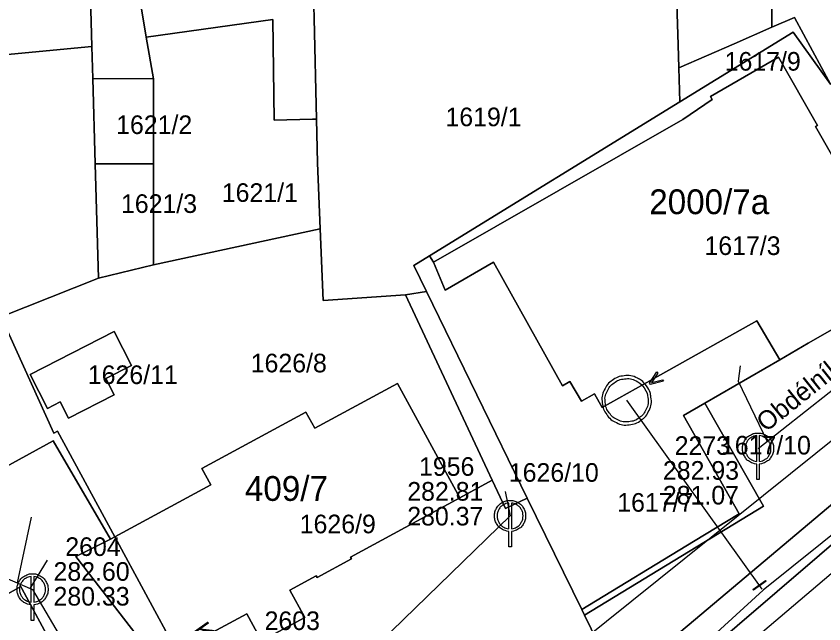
# Model space of a CAD drawing. Extents: x -570698 to -570232, y -1086952 to -1086596.
# Drawn here: x -570540.7 to -570475.5, y -1086825.7 to -1086776.7 of the extents above; entities that cross this region are included whole.
import ezdxf

# ---------------------------------------------------------------- set-up
doc = ezdxf.new("R2010")
doc.units = 0
for name, color, linetype in [('Adresní místo-text', 7, 'Continuous'), ('Armatura vodovodní', 7, 'Continuous'), ('Default', 7, 'Continuous'), ('Kanalizační přípojka', 7, 'Continuous'), ('Kanalizační stoka', 7, 'Continuous'), ('Kanalizační šachta', 7, 'Continuous'), ('Parcela-polygon', 7, 'Continuous'), ('Parcela-text', 7, 'Continuous'), ('Popis kmenové stoky', 7, 'Continuous'), ('Popis šachty', 7, 'Continuous'), ('Vodovodní přípojka', 7, 'Continuous'), ('Vodovodní řad', 7, 'Continuous'), ('Vodovodní šachta', 7, 'Continuous')]:
    doc.layers.add(name, color=color, linetype=linetype)

msp = doc.modelspace()

# ---------------------------------------------------------------- linework, layer by layer
at = {"layer": 'Armatura vodovodní'}
msp.add_lwpolyline([(-570480.197, -1086822.262), (-570481.212, -1086822.991), (-570481.257, -1086822.928), (-570480.242, -1086822.198), (-570480.197, -1086822.262)], dxfattribs=at)
at = {"layer": 'Default'}
for points in [[(-570489.836, -1086806.525), (-570489.544, -1086806.93), (-570489.475, -1086807.463), (-570489.406, -1086807.996), (-570489.636, -1086808.492), (-570489.867, -1086808.988), (-570490.289, -1086809.292), (-570490.705, -1086809.591), (-570491.239, -1086809.653), (-570491.774, -1086809.714), (-570492.261, -1086809.484), (-570492.749, -1086809.253), (-570493.05, -1086808.834), (-570493.347, -1086808.421), (-570493.41, -1086807.885), (-570493.473, -1086807.349), (-570493.244, -1086806.863), (-570493.015, -1086806.376), (-570492.598, -1086806.077), (-570492.176, -1086805.774), (-570491.635, -1086805.711), (-570491.093, -1086805.648), (-570490.61, -1086805.884), (-570490.127, -1086806.12), (-570489.836, -1086806.525)], [(-570490.035, -1086806.668), (-570490.289, -1086806.316), (-570490.713, -1086806.109), (-570491.137, -1086805.903), (-570491.611, -1086805.957), (-570492.085, -1086806.012), (-570492.455, -1086806.277), (-570492.818, -1086806.538), (-570493.019, -1086806.965), (-570493.22, -1086807.391), (-570493.166, -1086807.859), (-570493.111, -1086808.327), (-570492.85, -1086808.691), (-570492.585, -1086809.06), (-570492.159, -1086809.261), (-570491.732, -1086809.462), (-570491.264, -1086809.407), (-570490.796, -1086809.353), (-570490.432, -1086809.092), (-570490.063, -1086808.826), (-570489.862, -1086808.392), (-570489.661, -1086807.957), (-570489.721, -1086807.49), (-570489.78, -1086807.024), (-570490.035, -1086806.668)], [(-570489.359, -1086806.145), (-570489.414, -1086806.222), (-570489.463, -1086806.282), (-570489.382, -1086806.254), (-570489.298, -1086806.231)], [(-570480.953, -1086812.818), (-570481.211, -1086812.8), (-570481.473, -1086812.654), (-570481.77, -1086812.49), (-570481.935, -1086812.193), (-570482.1, -1086811.895), (-570482.1, -1086811.57), (-570482.1, -1086811.243), (-570481.932, -1086810.943), (-570481.763, -1086810.642), (-570481.465, -1086810.481), (-570481.167, -1086810.32), (-570480.85, -1086810.32), (-570480.535, -1086810.32), (-570480.236, -1086810.481), (-570479.937, -1086810.642), (-570479.768, -1086810.943), (-570479.6, -1086811.243), (-570479.6, -1086811.57), (-570479.6, -1086811.895), (-570479.765, -1086812.193), (-570479.93, -1086812.49), (-570480.227, -1086812.654), (-570480.489, -1086812.8), (-570480.747, -1086812.818)], [(-570480.953, -1086810.532), (-570481.15, -1086810.549), (-570481.365, -1086810.664), (-570481.614, -1086810.799), (-570481.753, -1086811.049), (-570481.892, -1086811.299), (-570481.892, -1086811.57), (-570481.892, -1086811.841), (-570481.756, -1086812.088), (-570481.619, -1086812.334), (-570481.37, -1086812.471), (-570481.158, -1086812.591), (-570480.953, -1086812.605)], [(-570480.747, -1086812.605), (-570480.542, -1086812.591), (-570480.328, -1086812.471), (-570480.081, -1086812.334), (-570479.944, -1086812.088), (-570479.808, -1086811.841), (-570479.808, -1086811.57), (-570479.808, -1086811.299), (-570479.948, -1086811.049), (-570480.088, -1086810.799), (-570480.337, -1086810.664), (-570480.55, -1086810.549), (-570480.747, -1086810.532)], [(-570500.943, -1086818.248), (-570501.201, -1086818.23), (-570501.463, -1086818.084), (-570501.76, -1086817.92), (-570501.925, -1086817.623), (-570502.09, -1086817.325), (-570502.09, -1086817), (-570502.09, -1086816.673), (-570501.922, -1086816.373), (-570501.753, -1086816.072), (-570501.455, -1086815.911), (-570501.157, -1086815.75), (-570500.84, -1086815.75), (-570500.525, -1086815.75), (-570500.226, -1086815.911), (-570499.927, -1086816.072), (-570499.758, -1086816.373), (-570499.59, -1086816.673), (-570499.59, -1086817), (-570499.59, -1086817.325), (-570499.755, -1086817.623), (-570499.92, -1086817.92), (-570500.217, -1086818.084), (-570500.479, -1086818.23), (-570500.737, -1086818.248)], [(-570500.943, -1086815.962), (-570501.14, -1086815.979), (-570501.355, -1086816.094), (-570501.604, -1086816.229), (-570501.743, -1086816.479), (-570501.882, -1086816.729), (-570501.882, -1086817), (-570501.882, -1086817.271), (-570501.746, -1086817.518), (-570501.609, -1086817.764), (-570501.36, -1086817.901), (-570501.148, -1086818.021), (-570500.943, -1086818.035)], [(-570500.737, -1086818.035), (-570500.532, -1086818.021), (-570500.318, -1086817.901), (-570500.071, -1086817.764), (-570499.934, -1086817.518), (-570499.798, -1086817.271), (-570499.798, -1086817), (-570499.798, -1086816.729), (-570499.938, -1086816.479), (-570500.078, -1086816.229), (-570500.327, -1086816.094), (-570500.54, -1086815.979), (-570500.737, -1086815.962)], [(-570539.443, -1086824.168), (-570539.701, -1086824.15), (-570539.963, -1086824.004), (-570540.26, -1086823.84), (-570540.425, -1086823.543), (-570540.59, -1086823.245), (-570540.59, -1086822.92), (-570540.59, -1086822.593), (-570540.422, -1086822.293), (-570540.253, -1086821.992), (-570539.955, -1086821.831), (-570539.657, -1086821.67), (-570539.34, -1086821.67), (-570539.025, -1086821.67), (-570538.726, -1086821.831), (-570538.427, -1086821.992), (-570538.258, -1086822.293), (-570538.09, -1086822.593), (-570538.09, -1086822.92), (-570538.09, -1086823.245), (-570538.255, -1086823.543), (-570538.42, -1086823.84), (-570538.717, -1086824.004), (-570538.979, -1086824.15), (-570539.237, -1086824.168)], [(-570539.443, -1086821.882), (-570539.64, -1086821.899), (-570539.855, -1086822.014), (-570540.104, -1086822.149), (-570540.243, -1086822.399), (-570540.382, -1086822.649), (-570540.382, -1086822.92), (-570540.382, -1086823.191), (-570540.246, -1086823.438), (-570540.109, -1086823.684), (-570539.86, -1086823.821), (-570539.648, -1086823.941), (-570539.443, -1086823.955)], [(-570539.237, -1086823.955), (-570539.032, -1086823.941), (-570538.818, -1086823.821), (-570538.571, -1086823.684), (-570538.434, -1086823.438), (-570538.298, -1086823.191), (-570538.298, -1086822.92), (-570538.298, -1086822.649), (-570538.438, -1086822.399), (-570538.578, -1086822.149), (-570538.827, -1086822.014), (-570539.04, -1086821.899), (-570539.237, -1086821.882)]]:
    msp.add_open_spline(points, degree=3, dxfattribs=at)
at = {"layer": 'Kanalizační přípojka'}
for points in [[(-570482.279, -1086804.912), (-570482.45, -1086806.15)], [(-570482.45, -1086806.15), (-570480.118, -1086810.992)], [(-570501.237, -1086815.04), (-570500.84, -1086817)], [(-570539.44, -1086817.11), (-570540.582, -1086822.397)], [(-570538.16, -1086820.56), (-570539.545, -1086822.838)]]:
    msp.add_lwpolyline(points, dxfattribs=at)
at = {"layer": 'Kanalizační stoka'}
msp.add_line((-570516.073, -1086843.915), (-570416.01, -1086763.66), dxfattribs=at)
for points in [[(-570480.85, -1086811.57), (-570469.4, -1086802.53), (-570457.95, -1086793.49)], [(-570483.53, -1086828.91), (-570466.92, -1086814.815), (-570450.31, -1086800.72)], [(-570500.84, -1086817), (-570516.12, -1086831.85)], [(-570541.982, -1086821.803), (-570539.34, -1086822.925)], [(-570539.34, -1086822.925), (-570534.7, -1086830.82)]]:
    msp.add_lwpolyline(points, dxfattribs=at)
at = {"layer": 'Kanalizační šachta'}
for points in [[(-570480.953, -1086812.605), (-570480.953, -1086810.532)], [(-570480.747, -1086810.532), (-570480.747, -1086812.605)], [(-570480.747, -1086812.818), (-570480.747, -1086814.07), (-570480.953, -1086814.07), (-570480.953, -1086812.818)], [(-570500.943, -1086818.035), (-570500.943, -1086815.962)], [(-570500.737, -1086815.962), (-570500.737, -1086818.035)], [(-570500.737, -1086818.248), (-570500.737, -1086819.5), (-570500.943, -1086819.5), (-570500.943, -1086818.248)], [(-570539.443, -1086823.955), (-570539.443, -1086821.882)], [(-570539.237, -1086821.882), (-570539.237, -1086823.955)], [(-570539.237, -1086824.168), (-570539.237, -1086825.42), (-570539.443, -1086825.42), (-570539.443, -1086824.168)]]:
    msp.add_lwpolyline(points, dxfattribs=at)
at = {"layer": 'Parcela-polygon'}
for points in [[(-570291.64, -1086688.892), (-570302.37, -1086696.04), (-570396.95, -1086758.9), (-570417.85, -1086767.9), (-570426.99, -1086775.07), (-570430.55, -1086777.63), (-570432.81, -1086779.33), (-570437.1, -1086782.56), (-570450.62, -1086793.64), (-570452.87, -1086797.51), (-570456.3, -1086803.42), (-570469.27, -1086814.47), (-570499.22, -1086840.17), (-570503.94, -1086844.12), (-570508.33, -1086847.72), (-570512.7, -1086850.77), (-570519.4, -1086855.31), (-570522.96, -1086857.62), (-570528.66, -1086861.02), (-570535.32, -1086864.67), (-570544.494, -1086869.551)], [(-570516.84, -1086768.72), (-570516.64, -1086776.92), (-570516.45, -1086785.02), (-570516.36, -1086788.54), (-570516.14, -1086793.85), (-570515.9, -1086799.64), (-570509.28, -1086799.19), (-570507.59, -1086798.91), (-570508.61, -1086796.82), (-570507.34, -1086796.04), (-570487.15, -1086783.62), (-570487.24, -1086780.88), (-570487.29, -1086779.03), (-570487.44, -1086773.99)], [(-570544.494, -1086869.551), (-570535.32, -1086864.67), (-570528.66, -1086861.02), (-570522.96, -1086857.62), (-570519.4, -1086855.31), (-570512.7, -1086850.77), (-570508.33, -1086847.72), (-570503.94, -1086844.12), (-570499.22, -1086840.17), (-570469.27, -1086814.47), (-570456.3, -1086803.42), (-570452.87, -1086797.51), (-570485.9, -1086825.32), (-570492.12, -1086830.55), (-570513.86, -1086848.7), (-570520.15, -1086853.96), (-570542.94, -1086866), (-570545.975, -1086867.584)], [(-570468.67, -1086798.42), (-570476.82, -1086803.09), (-570479.1, -1086804.43), (-570485.13, -1086807.9), (-570480.4, -1086816.21), (-570494.84, -1086825), (-570492.12, -1086830.55), (-570485.9, -1086825.32), (-570452.87, -1086797.51)], [(-570568.236, -1086838.021), (-570542.59, -1086823.97), (-570547, -1086816.06), (-570537.68, -1086810.96), (-570533.06, -1086818.87), (-570532.7, -1086818.69), (-570537.33, -1086810.17), (-570537.63, -1086810.34), (-570541.87, -1086800.95), (-570571.88, -1086812.78), (-570570.98, -1086827.68), (-570570.535, -1086834.968)], [(-570545.975, -1086867.584), (-570542.94, -1086866), (-570520.15, -1086853.96), (-570513.86, -1086848.7), (-570535.84, -1086820.27), (-570533.06, -1086818.87), (-570537.68, -1086810.96), (-570547, -1086816.06), (-570542.59, -1086823.97), (-570540.28, -1086822.7), (-570540.19, -1086822.86), (-570530.15, -1086841.46), (-570555.373, -1086855.104)], [(-570555.373, -1086855.104), (-570530.15, -1086841.46), (-570540.19, -1086822.86), (-570540.28, -1086822.7), (-570542.59, -1086823.97), (-570568.236, -1086838.021)]]:
    msp.add_lwpolyline(points, dxfattribs=at)
for points in [[(-570538.98, -1086751.22), (-570541.1, -1086771.74), (-570576.24, -1086767.98), (-570574.78, -1086782.97), (-570568.21, -1086782.35), (-570534.55, -1086779.16), (-570535.32, -1086751.53)], [(-570535.32, -1086751.53), (-570534.55, -1086779.16), (-570534.47, -1086781.74), (-570529.59, -1086781.76), (-570530.17, -1086778.41), (-570531.51, -1086770.26), (-570531.68, -1086762.98), (-570531.29, -1086759.87), (-570530.75, -1086752.07)], [(-570530.75, -1086752.07), (-570531.29, -1086759.87), (-570531.68, -1086762.98), (-570531.51, -1086770.26), (-570530.17, -1086778.41), (-570519.97, -1086777), (-570519.85, -1086785.1), (-570516.78, -1086785.02), (-570516.45, -1086785.02), (-570516.64, -1086776.92), (-570516.84, -1086768.72), (-570517.12, -1086757.38), (-570517.21, -1086753.48)], [(-570487.97, -1086756.56), (-570487.83, -1086761.17), (-570487.72, -1086764.85), (-570479.93, -1086765.93), (-570479.67, -1086764.1), (-570479.5, -1086762.88), (-570477.97, -1086763.08), (-570477.77, -1086761.55), (-570467.33, -1086762.82), (-570468.61, -1086773.22), (-570473.69, -1086772.58), (-570473.67, -1086772.43), (-570479.75, -1086771.68), (-570479.73, -1086777.62), (-570477.91, -1086776.82), (-570475.02, -1086782.19), (-570473.93, -1086782.13), (-570454.98, -1086781.11), (-570451.54, -1086760.42)], [(-570479.93, -1086765.93), (-570487.72, -1086764.85), (-570487.61, -1086768.44), (-570487.52, -1086771.42), (-570487.44, -1086773.99), (-570487.29, -1086779.03), (-570487.24, -1086780.88), (-570482.77, -1086778.94), (-570479.73, -1086777.62), (-570479.75, -1086771.68), (-570473.67, -1086772.43), (-570473.69, -1086772.58), (-570468.61, -1086773.22), (-570467.33, -1086762.82), (-570477.77, -1086761.55), (-570477.97, -1086763.08), (-570479.5, -1086762.88), (-570479.67, -1086764.1)], [(-570516.36, -1086788.54), (-570516.45, -1086785.02), (-570516.78, -1086785.02), (-570519.85, -1086785.1), (-570519.97, -1086777), (-570530.17, -1086778.41), (-570529.59, -1086781.76), (-570529.58, -1086788.63), (-570529.58, -1086796.76), (-570516.14, -1086793.85)], [(-570475.02, -1086782.19), (-570477.91, -1086776.82), (-570479.73, -1086777.62), (-570482.77, -1086778.94), (-570487.24, -1086780.88), (-570487.15, -1086783.62), (-570478.02, -1086778)], [(-570484.67, -1086783.2), (-570479.19, -1086780.03), (-570476.05, -1086785.53), (-570476.22, -1086785.62), (-570472.06, -1086792.9), (-570471.89, -1086792.8), (-570468.67, -1086798.42), (-570466.77, -1086796.78), (-570473.66, -1086782.68), (-570473.93, -1086782.13), (-570475.02, -1086782.19), (-570478.02, -1086778), (-570487.15, -1086783.62), (-570507.34, -1086796.04), (-570507.02, -1086796.56), (-570486.92, -1086785.04), (-570484.54, -1086783.43)], [(-570534.28, -1086788.61), (-570534.47, -1086781.74), (-570534.55, -1086779.16), (-570568.21, -1086782.35), (-570567.83, -1086786.02), (-570574.42, -1086786.67), (-570574.22, -1086788.74), (-570571.88, -1086812.78), (-570541.87, -1086800.95), (-570534.03, -1086797.85)], [(-570479.19, -1086780.03), (-570484.67, -1086783.2), (-570484.54, -1086783.43), (-570486.92, -1086785.04), (-570507.02, -1086796.56), (-570506.08, -1086798.81), (-570502.19, -1086796.56), (-570496.61, -1086806.52), (-570496.03, -1086806.18), (-570495.08, -1086807.75), (-570494.04, -1086807.16), (-570493.41, -1086808.26), (-570488.72, -1086805.63), (-570480.95, -1086801.28), (-570479.1, -1086804.43), (-570476.82, -1086803.09), (-570468.67, -1086798.42), (-570471.89, -1086792.8), (-570472.06, -1086792.9), (-570476.22, -1086785.62), (-570476.05, -1086785.53)], [(-570534.47, -1086781.74), (-570534.28, -1086788.61), (-570529.58, -1086788.63), (-570529.59, -1086781.76)], [(-570529.58, -1086788.63), (-570534.28, -1086788.61), (-570534.03, -1086797.85), (-570529.58, -1086796.76)], [(-570516.14, -1086793.85), (-570529.58, -1086796.76), (-570534.03, -1086797.85), (-570541.87, -1086800.95), (-570537.63, -1086810.34), (-570537.33, -1086810.17), (-570532.7, -1086818.69), (-570524.97, -1086814.49), (-570525.69, -1086813.18), (-570517.3, -1086808.64), (-570516.59, -1086809.94), (-570509.92, -1086806.32), (-570504.9, -1086815.55), (-570502.28, -1086814.13), (-570509.28, -1086799.19), (-570515.9, -1086799.64)], [(-570486.86, -1086808.9), (-570485.13, -1086807.9), (-570479.1, -1086804.43), (-570480.95, -1086801.28), (-570488.72, -1086805.63), (-570493.41, -1086808.26), (-570494.04, -1086807.16), (-570495.08, -1086807.75), (-570496.03, -1086806.18), (-570496.61, -1086806.52), (-570502.19, -1086796.56), (-570506.08, -1086798.81), (-570507.02, -1086796.56), (-570507.34, -1086796.04), (-570508.61, -1086796.82), (-570507.59, -1086798.91), (-570499.45, -1086815.57), (-570495.06, -1086824.55), (-570486.04, -1086819.06), (-570482.36, -1086816.82)], [(-570499.45, -1086815.57), (-570507.59, -1086798.91), (-570509.28, -1086799.19), (-570502.28, -1086814.13), (-570501.22, -1086816.39)], [(-570531.36, -1086804.87), (-570533.42, -1086805.93), (-570532.75, -1086807.25), (-570536.44, -1086809.13), (-570537.12, -1086807.81), (-570538.13, -1086808.33), (-570539.52, -1086805.61), (-570532.75, -1086802.15)], [(-570539.52, -1086805.61), (-570538.13, -1086808.33), (-570537.12, -1086807.81), (-570536.44, -1086809.13), (-570532.75, -1086807.25), (-570533.42, -1086805.93), (-570531.36, -1086804.87), (-570532.75, -1086802.15)], [(-570513.7, -1086820.33), (-570504.9, -1086815.55), (-570509.92, -1086806.32), (-570516.59, -1086809.94), (-570517.3, -1086808.64), (-570525.69, -1086813.18), (-570524.97, -1086814.49), (-570532.7, -1086818.69), (-570527.71, -1086827.94), (-570522.06, -1086824.88), (-570520.87, -1086827.06), (-570517.39, -1086825.19), (-570518.59, -1086822.99), (-570516.47, -1086821.84), (-570516.4, -1086821.96), (-570513.63, -1086820.46)], [(-570480.4, -1086816.21), (-570485.13, -1086807.9), (-570486.86, -1086808.9), (-570482.36, -1086816.82), (-570486.04, -1086819.06), (-570495.06, -1086824.55), (-570494.84, -1086825)], [(-570494.84, -1086825), (-570495.06, -1086824.55), (-570499.45, -1086815.57), (-570501.22, -1086816.39), (-570502.28, -1086814.13), (-570504.9, -1086815.55), (-570513.7, -1086820.33), (-570513.63, -1086820.46), (-570516.4, -1086821.96), (-570516.47, -1086821.84), (-570518.59, -1086822.99), (-570517.39, -1086825.19), (-570520.87, -1086827.06), (-570522.06, -1086824.88), (-570527.71, -1086827.94), (-570532.7, -1086818.69), (-570533.06, -1086818.87), (-570535.84, -1086820.27), (-570513.86, -1086848.7), (-570492.12, -1086830.55)]]:
    msp.add_lwpolyline(points, close=True, dxfattribs=at)
at = {"layer": 'Vodovodní přípojka'}
msp.add_line((-570480.504, -1086822.905), (-570491.441, -1086807.682), dxfattribs=at)
at = {"layer": 'Vodovodní řad'}
msp.add_lwpolyline([(-570429.328, -1086757.943), (-570424.039, -1086777.75), (-570480.425, -1086822.995), (-570494.455, -1086835.799), (-570516.511, -1086852.784), (-570525.384, -1086857.882), (-570544.749, -1086867.64), (-570545.576, -1086868.114)], dxfattribs=at)
at = {"layer": 'Vodovodní šachta'}
for points in [[(-570489.594, -1086806.293), (-570489.005, -1086805.39), (-570488.922, -1086805.506), (-570489.359, -1086806.145)], [(-570489.298, -1086806.231), (-570488.549, -1086806.025), (-570488.469, -1086806.136), (-570489.514, -1086806.404), (-570489.594, -1086806.293)]]:
    msp.add_lwpolyline(points, dxfattribs=at)

# ---------------------------------------------------------------- texts
at = {"layer": 'Adresní místo-text'}
for s, p in [('2000/7a', (-570489.618, -1086792.68)), ('409/7', (-570522.215, -1086815.79))]:
    msp.add_text(s, height=2, dxfattribs=at).set_placement(p)
at = {"layer": 'Parcela-text'}
for s, p in [('1617/9', (-570483.54, -1086781.11)), ('1619/1', (-570506.05, -1086785.59)), ('1621/2', (-570532.6, -1086786.22)), ('1621/1', (-570524.08, -1086791.69)), ('1621/3', (-570532.21, -1086792.58)), ('1617/3', (-570485.17, -1086795.97)), ('1626/8', (-570521.75, -1086805.43)), ('1626/11', (-570534.88, -1086806.37)), ('1617/10', (-570483.84, -1086812.05)), ('1626/10', (-570500.94, -1086814.25)), ('1617/7', (-570492.2, -1086816.66)), ('1626/9', (-570517.8, -1086818.4))]:
    msp.add_text(s, height=1.5, dxfattribs=at).set_placement(p)
at = {"layer": 'Popis kmenové stoky'}
for s, rotation, p in [('Obdélníkové 2000/1500 TB', 38.73114, (-570480.212, -1086810.294)), ('Kruhové 400 TB', 305.24321, (-570526.527, -1086826.232))]:
    msp.add_text(s, height=1.5, rotation=rotation, dxfattribs=at).set_placement(p)
at = {"layer": 'Popis šachty'}
for s, p in [('2273', (-570487.57, -1086812.082)), ('1956', (-570508.18, -1086813.769)), ('282.93', (-570488.519, -1086814.082)), ('282.81', (-570509.129, -1086815.769)), ('281.07', (-570488.519, -1086816.082)), ('280.37', (-570509.129, -1086817.769)), ('2604', (-570536.697, -1086820.228)), ('282.60', (-570537.647, -1086822.228)), ('280.33', (-570537.647, -1086824.228)), ('2603', (-570520.631, -1086826.2))]:
    msp.add_text(s, height=1.5, dxfattribs=at).set_placement(p)

doc.saveas('drawing.dxf')
